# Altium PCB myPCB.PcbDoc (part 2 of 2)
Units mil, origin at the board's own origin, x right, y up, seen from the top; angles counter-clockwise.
Board outline 3914 x 3499.3 mil, 2 copper layers (Top Layer, Bottom Layer); 61 components, 196 nets, 504 pads, 76 vias.
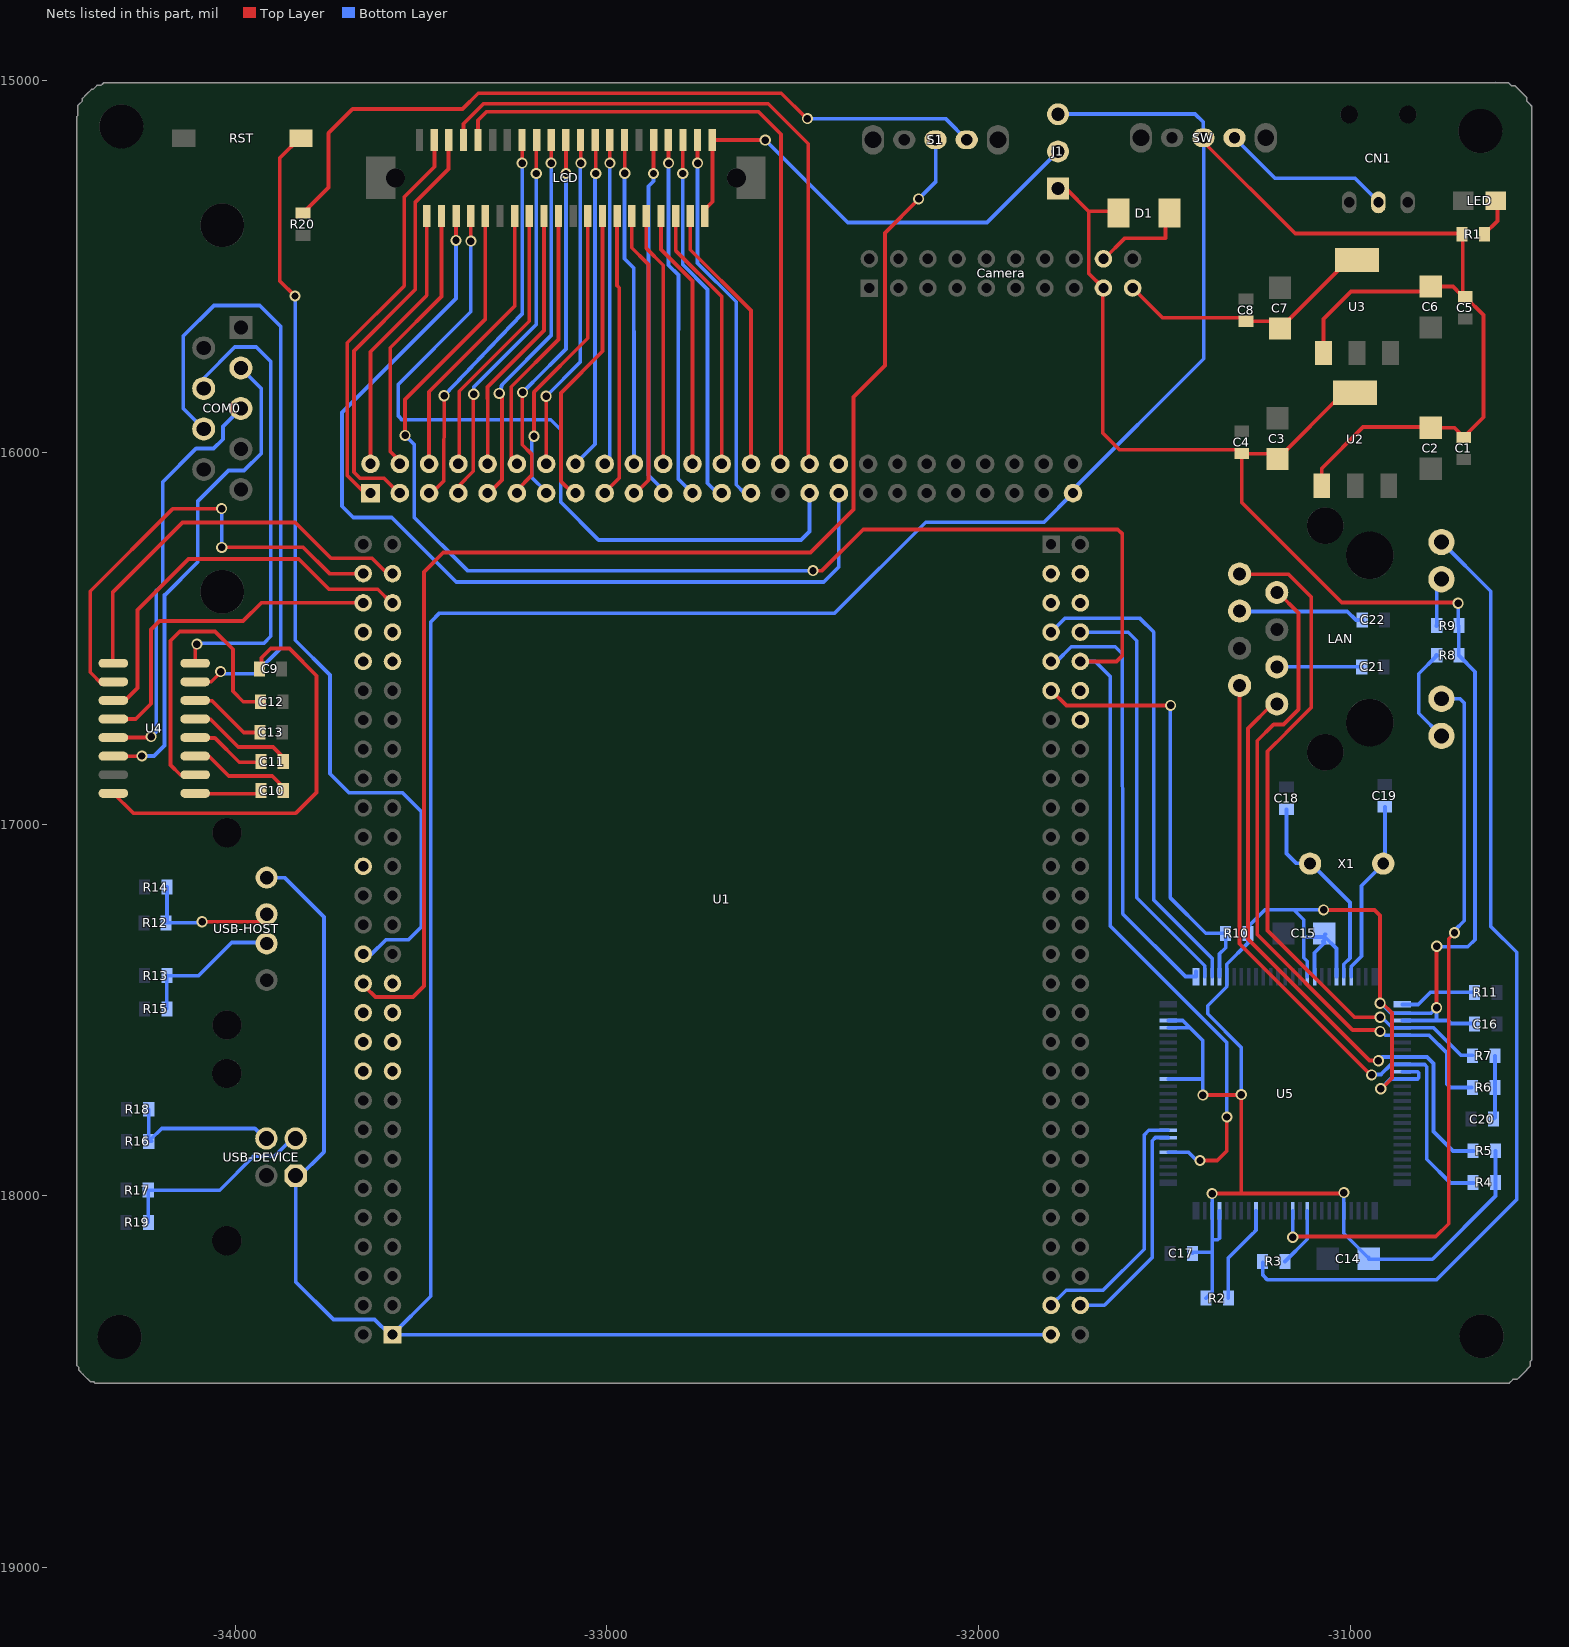
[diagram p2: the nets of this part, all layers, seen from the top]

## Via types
v1: diameter 30, hole 20, Top Layer to Bottom Layer, 75 vias
v2: diameter 30, hole 20, Top Layer to Bottom Layer, tented top, 1 vias

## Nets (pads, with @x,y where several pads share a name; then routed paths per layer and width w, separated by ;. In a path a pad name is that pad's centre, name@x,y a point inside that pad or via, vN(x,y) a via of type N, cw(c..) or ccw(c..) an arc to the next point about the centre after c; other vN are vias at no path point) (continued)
LDATA14: U1.PC53 U5.83 | length 690.5
  Bottom Layer w10: U1.PC53@-31805.13,-18294.87 -31764.51,-18254.24 -31665.07,-18254.24 -31554.69,-18143.85 -31554.69,-17836.42 -31542.12,-17823.86 U5.83@-31489.87,-17823.86
LDATA15: U1.PC54 U5.82 | length 607.4
  Bottom Layer w10: U1.PC54@-31726.39,-18294.87 -31661.68,-18294.87 -31533.08,-18166.26 -31533.08,-17852.21 -31524.41,-17843.54 U5.82@-31489.87,-17843.54
LEND: U1.PB34
LNGCS1: U1.PC3
LNGCS2: U1.PC5
LNGCS3: U1.PC4
LNGCS4: U1.PC7 U5.3 | length 1298.6
  Bottom Layer w10: U1.PC7@-31805.13,-16483.84 -31768.11,-16446.82 -31566.03,-16446.82 -31529.07,-16483.77 -31529.07,-16493.32 -31529.12,-17168.46 -31529.12,-17204.69 -31371.76,-17362.05 U5.3@-31371.76,-17410.47
LNOE: U1.PC9 U5.1 | length 1196.2
  Bottom Layer w10: U1.PC9@-31805.13,-16562.58 -31790.16,-16562.58 -31750.81,-16523.24 -31632.2,-16523.24 -31613.44,-16542 -31613.44,-16560.89 -31612.32,-17241.7 -31443.55,-17410.47 U5.1@-31415.06,-17410.47 U5.1@-31415.06,-17396.94
LNWBE1: U1.PC6
LNWE: U1.PC8 U5.2 | length 1140.9
  Bottom Layer w10: U1.PC8@-31726.39,-16483.84 -31597.49,-16483.84 -31574.45,-16506.88 -31574.45,-16509.06 -31574.38,-17182.39 -31574.38,-17198.34 -31391.44,-17381.28 U5.2@-31391.44,-17410.47
M_NRESET: RST.1 U1.PA28 | length 2589.4
  Top Layer w10: v1(-33839.13,-15579.5) -33880.4,-15538.23 -33880.4,-15208.79 -33823.2,-15151.59 RST.1@-33823.2,-15160.13
  Bottom Layer w10: v1@-33838.78,-15575.77 -33838.23,-15576.31 -33838.23,-16505.61 -33744.71,-16599.13 -33744.71,-16864.7 -33693.73,-16915.68 -33549.97,-16915.68 -33499.52,-16966.13 -33499.52,-17277 -33533.59,-17311.07 -33594.28,-17311.07 -33633.19,-17349.98 U1.PA28@-33655.53,-17349.98
NCTS0: U1.PA53 U4.9 | length 1085.4
  Top Layer w10: U4.9@-34327.69,-16567.44 -34329,-16566.13 -34329,-16376 -34141.97,-16188.97 -33838.12,-16188.97 -33741.85,-16285.24 -33632.17,-16285.24 -33591.04,-16326.36 U1.PA53@-33576.79,-16326.36 U1.PA53@-33576.79,-16319.49
NETACT: LAN.10 U5.62 | length 1991.1
  Top Layer w10: v1@-31156.35,-18109.93 -30769.96,-18109.93 -30735.34,-18075.31 -30735.34,-17308.52 v1@-30719.9,-17293.08
  Bottom Layer w10: U5.62@-31155.22,-18040.39 -31155.22,-18111.48 v1(-31155.03,-18111.67) ; LAN.10@-30754.84,-16663.02 -30704.77,-16663.02 -30693.48,-16674.31 -30693.48,-17260.36 -30718.16,-17285.04 v1@-30718.16,-17293.79
  other v1: -30719.81,-17292.55
NetC10_1: C10.1 U4.3 | length 290.7
  Top Layer w10: U4.3@-34123.69,-16818.44 -34107.69,-16818.44 -34069.56,-16818.44 -34017,-16871 -33900,-16871 C10.1@-33868,-16903
NetC10_2: C10.2 U4.1 | length 193.1
  Top Layer w10: U4.1@-34123.69,-16918.44 -34107.69,-16918.44 -33935.44,-16918.44 C10.2@-33932,-16915
NetC11_1: C11.1 U4.5 | length 294.8
  Top Layer w10: U4.5@-34123.69,-16718.44 -34107.69,-16718.44 -34066.56,-16718.44 -33992,-16793 -33898,-16793 C11.1@-33871,-16820
NetC11_2: C11.2 U4.4 | length 218.8
  Top Layer w10: U4.4@-34123.69,-16768.44 -34107.69,-16768.44 -34054.56,-16768.44 -33989,-16834 C11.2@-33932,-16834
NetC12_2: C12.2 U4.2 | length 808.6
  Top Layer w10: U4.2@-34107.69,-16867.44 -34147.56,-16867.44 -34174,-16841 -34174,-16507 -34149,-16482 -34054,-16482 -34006,-16530 -34006,-16643 -33978,-16671 ; -33978.21,-16671.21 C12.2@-33931.74,-16671.21
NetC13_2: C13.2 U4.6 | length 225.1
  Top Layer w10: U4.6@-34123.69,-16668.44 -34107.69,-16668.44 -34062.56,-16668.44 -33977,-16754 C13.2@-33934,-16754
NetC18_1: C18.1 U5.21 X1.1 | length 550.6
  Bottom Layer w10: C18.1@-31171.58,-16960.26 -31171.58,-17079.57 -31145.94,-17105.21 -31106.79,-17105.21 -31000.78,-17211.22 -31000.78,-17360.81 -31017.46,-17377.49 U5.21@-31017.46,-17410.29
NetC19_1: C19.1 U5.22 X1.2 | length 494.8
  Bottom Layer w10: U5.22@-30997.74,-17410.47 -30997.74,-17383.23 -30970.22,-17355.71 -30970.22,-17166.22 -30906.79,-17102.79 -30906.79,-16954.28 C19.1@-30907.42,-16953.65
NetC20_1: C20.1 R6.1 R7.1 | length 169.8
  Bottom Layer w10: C20.1@-30613.78,-17792.09 -30611.01,-17789.33 R6.1@-30611.01,-17708.68 R7.1@-30611.01,-17623.48
NetC21_1: C21.1 LAN.3 | length 229.9
  Bottom Layer w10: LAN.3@-31197.76,-16577.2 -30968.43,-16577.2 C21.1@-30968.03,-16577.59
NetC22_1: C22.1 LAN.6 | length 340.3
  Bottom Layer w10: LAN.6@-31298,-16428 -31008,-16428 -30984.6,-16451.4 C22.1@-30967.38,-16451.4
NetCN1_2: CN1.2 SW.2 | length 480.8
  Top Layer w10: CN1.2@-30936.09,-15343.93 -30924.48,-15332.33 CN1.2@-30924.48,-15327.53
  Bottom Layer w10: SW.2@-31311.36,-15153.89 -31202.48,-15262.76 -30987.44,-15262.76 CN1.2@-30923.37,-15326.83
NetLAN_9: LAN.9 R8.1 | length 262
  Bottom Layer w10: R8.1@-30769.24,-16546.76 R8.1@-30768,-16545.53 ; R8.1@-30768,-16548 -30816,-16596 -30816,-16701.87 LAN.9@-30754.84,-16763.02
NetLAN_11: LAN.11 R9.1 | length 132.9
  Bottom Layer w10: R9.1@-30768,-16468 -30766.74,-16466.74 -30767.67,-16465.8 -30767.67,-16354.2 LAN.11@-30754.84,-16341.37
NetLED_1: LED.1 R1.1 | length 96.1
  Top Layer w10: R1.1@-30639.47,-15413.42 -30604,-15377.95 LED.1@-30604,-15332
NETLINK: LAN.12 R3.1 | length 2670
  Bottom Layer w10: R3.1@-31235.61,-18179.73 -31235.92,-18180.05 -31235.92,-18212.18 -31235.22,-18212.89 ; -31234.93,-18213.95 -31222.52,-18226.36 -30768.79,-18226.36 -30588.89,-18046.46 ; LAN.12@-30756,-16242 LAN.12@-30755.74,-16242.26 ; LAN.12@-30756,-16240 -30621.96,-16374.04 -30621.96,-17275.58 -30552.46,-17345.08 -30552.46,-17365.13 ; -30589.49,-18047 -30552.36,-18009.88 -30552.36,-17361.5
NetR2_1: R2.1 U5.67 | length 266.5
  Bottom Layer w10: R2.1@-31328.1,-18275.59 -31328.1,-18166.74 -31263.46,-18102.1 -31262.73,-18102.1 -31253.65,-18093.01 U5.67@-31253.65,-18040.39
NetR3_2: R3.2 U5.60 | length 168.1
  Bottom Layer w10: R3.2@-31175.92,-18176.81 -31115.89,-18116.77 -31115.89,-18094.17 ; -31115.86,-18101.46 U5.60@-31115.86,-18040.9
NetR11_2: R11.2 U5.26 | length 210.7
  Bottom Layer w10: U5.26@-30859.94,-17485.28 -30817.04,-17485.28 -30784.62,-17452.85 R11.2@-30662.67,-17452.85
NetR12_1: R12.1 R14.1 USB-HOST.2 | length 374.4
  Top Layer w10: v1(-34088.87,-17262.79) -33936.07,-17262.79 USB-HOST.2@-33917.08,-17243.79
  Bottom Layer w10: R12.1@-34185.63,-17265.97 -34093.5,-17265.97 v1@-34088.88,-17261.34 ; R14.1@-34183.47,-17169.58 -34183.47,-17263.53 R12.1@-34182,-17265
NetR13_1: R13.1 R15.1 USB-HOST.3 | length 398.9
  Bottom Layer w10: R15.1@-34183.69,-17497.31 -34183.69,-17411.83 -34185.55,-17409.97 R13.1@-34183.52,-17407.94 ; R13.1@-34183.69,-17407.94 R13.1@-34183.52,-17407.94 ; R13.1@-34182.63,-17407.05 R13.1@-34183.52,-17407.94 ; USB-HOST.3@-33914.07,-17318.51 -34009.43,-17318.51 -34098.87,-17407.94 R13.1@-34183.52,-17407.94
NetR16_2: R16.2 R18.2 USB-DEVICE.3 | length 450.1
  Bottom Layer w10: R18.2@-34232.54,-17767.36 -34232.54,-17845.46 R16.2@-34228.39,-17849.61 ; USB-DEVICE.3@-33924.76,-17853.76 -33916.55,-17845.55 USB-DEVICE.3@-33916,-17845 ; USB-DEVICE.3@-33919,-17847 -33947,-17819 -34197.78,-17819 R16.2@-34228.39,-17849.61 ; R16.2@-34228.39,-17849.61 R16.2@-34232.54,-17853.76 -34224.24,-17853.76 R16.2@-34228.39,-17849.61
NetR17_2: R17.2 R19.1 USB-DEVICE.2 | length 533.2
  Bottom Layer w10: R19.1@-34233.95,-18070.42 -34233.63,-18070.1 R17.2@-34233.63,-17985.03 -34041.53,-17985.03 -33950.5,-17894 -33894,-17894 -33845,-17845 USB-DEVICE.2@-33844,-17845
NetR20_1: R20.1 S1.4 | length 2055.5
  Top Layer w10: R20.1@-33817.71,-15356.6 -33748.91,-15287.8 -33748.91,-15141.34 -33684.03,-15076.46 -33388.48,-15076.46 -33345.83,-15033.81 -32530.76,-15033.81 v1@-32464.46,-15100.12
  Bottom Layer w10: v1(-32460.54,-15102.37) -32089.07,-15102.37 S1.4@-32029.82,-15161.61
NRESET: LCD.10 U1.PC10 U5.80 | length 5061.1
  Top Layer w10: v1(-33542.84,-15954.71) -33543.31,-15857.81 -33326.87,-15641.37 LCD.10@-33326.87,-15364.16 ; v1(-32445.51,-16318.33) -32421.42,-16318.33 -32310.52,-16207.42 -31625.47,-16207.42 -31613.26,-16219.62 -31613.26,-16546.57 -31629.27,-16562.58 U1.PC10@-31726.39,-16562.58 U1.PC10@-31726.39,-16569.6 ; v2(-31404.42,-17905.16) -31357.96,-17905.16 -31332.24,-17879.44 v1(-31332.24,-17788.1)
  Bottom Layer w10: v1(-33542.84,-15954.71) -33518.28,-15979.26 -33518.28,-16175.26 -33375.22,-16318.33 v1(-32445.51,-16318.33) ; U1.PC10@-31726.39,-16562.58 -31686.15,-16562.58 -31646.21,-16602.52 -31646.21,-17273.63 -31332.24,-17587.6 v1(-31332.24,-17788.1) ; U5.80@-31489.87,-17882.91 -31435.12,-17882.91 -31412.88,-17905.16 v2(-31404.42,-17905.16)
NRTS0: U1.PA54 U4.10 | length 1226.9
  Top Layer w10: U4.10@-34358,-16624 -34390,-16592 -34390,-16374 -34168.23,-16152.23 v1@-34037.23,-16152.23 ; v1(-34036.21,-16255.78) -33817.15,-16255.78 -33746.56,-16326.36 U1.PA54@-33655.53,-16326.36
  Bottom Layer w10: v1(-34036.21,-16255.78) v1@-34036.21,-16151.65 ; U1.PA54@-33655.53,-16326.36 U1.PA54@-33650.52,-16326.36
  other v1: -34036.43,-16151.43
NWAIT: R10.2 U1.PC11 U5.4 | length 1167.5
  Top Layer w10: U1.PC11@-31805.13,-16641.32 -31803.66,-16641.32 -31763.92,-16681.06 v1(-31483.46,-16681.06)
  Bottom Layer w10: v1(-31483.46,-16681.06) -31484.13,-16681.73 -31484.13,-17198.71 -31388.76,-17294.08 R10.2@-31335.37,-17294.08 -31335.37,-17332.56 -31351.71,-17348.91 -31351.71,-17373.43 ; U5.4@-31352.07,-17410.47 U5.4@-31352.07,-17410 ; U5.4@-31352,-17410 -31352,-17373.43
NXDACK0: U1.PC12
NXDREQ0: U1.PC14
OM0: S1.3 U1.PA26 | length 3631.4
  Top Layer w10: U1.PA26@-33649.86,-17428.72 -33649.86,-17438.42 -33622.84,-17465.44 -33521.57,-17465.44 -33492.11,-17435.98 -33492.11,-16321.8 -33440.13,-16269.82 -32452.44,-16269.82 -32336.76,-16154.14 -32336.76,-15851.12 -32252,-15766.36 -32252,-15664.07 ; -32251.95,-15664.02 -32251.95,-15409.98 v1@-32160.9,-15318.92
  Bottom Layer w10: U1.PA26@-33655.53,-17428.72 U1.PA26@-33640.24,-17428.72 ; v1(-32161.49,-15318.32) -32114.98,-15271.81 S1.3@-32114.98,-15159.29
RSCTS0: COM0.7 U4.8 | length 1246
  Top Layer w10: U4.8@-34107.69,-16567.44 -34107.69,-16529.69 v1@-34106,-16528
  Bottom Layer w10: v1@-34104,-16514 -33922.87,-16514 -33904,-16495.13 -33904,-15756 -33943,-15717 -34001,-15717 -34084.63,-15800.63 COM0.7@-34084.63,-15828.16
  other v1: -34103,-16516
RSRTS0: COM0.8 U4.7 | length 1769.6
  Top Layer w10: U4.7@-34123.69,-16618.44 U4.7@-34082.44,-16618.44 ; U4.7@-34107.69,-16617.44 -34064.44,-16617.44 v1@-34039,-16592
  Bottom Layer w10: COM0.8@-34084.63,-15937.16 -34140,-15881.79 -34140,-15688 -34057,-15605 -33934,-15605 -33877,-15662 -33877,-16526.11 -33946.89,-16596 v1@-34040,-16596
  other v1: -34039,-16590
RSRXD0: COM0.3 U4.13 | length 1108.4
  Top Layer w10: U4.13@-34327.69,-16767.44 -34229.44,-16767.44 v1@-34229,-16767
  Bottom Layer w10: v1(-34226,-16765) -34212,-16751 -34212,-16371 ; -34210,-16371 -34195,-16356 -34195,-16080 -34105,-15990 -34058,-15990 -34033,-15965 -34033,-15930.53 COM0.3@-33984.63,-15882.16
RSTXD0: COM0.2 U4.14 | length 1306.4
  Top Layer w10: U4.14@-34327.69,-16817.44 -34266.56,-16817.44 -34266,-16818
  Bottom Layer w10: v1(-34251,-16817) -34218,-16817 -34190,-16789 -34190,-16388 ; -34190,-16384 -34189,-16384 -34101,-16296 -34101,-16132 -34018,-16049 -33976,-16049 -33930,-16003 -33930,-15828 -33984.73,-15773.27 COM0.2@-33988,-15770
RX+: LAN.8 R7.2 U5.29 | length 1854.3
  Top Layer w10: LAN.8@-31298,-16328 -31166,-16328 -31105.01,-16388.99 -31105.01,-16686.46 -31172.47,-16753.92 ; -31172.67,-16754.29 -31222.56,-16804.19 -31222.56,-17286.46 -30989.03,-17520 v1(-30920,-17520)
  Bottom Layer w10: v1(-30920,-17520) -30915.45,-17520 -30887.19,-17548.27 U5.29@-30859.94,-17548.27 ; U5.29@-30859.94,-17548 -30775.94,-17548 -30701.53,-17622.41 R7.2@-30671.47,-17622.41
RX-: LAN.7 R6.2 U5.30 | length 1802
  Top Layer w10: LAN.7@-31194,-16378 -31139.62,-16432.38 -31139.62,-16691.62 -31180,-16732 -31206.36,-16732 -31250.36,-16776 -31250.36,-17297.44 -30993.8,-17554 v1@-30920,-17554
  Bottom Layer w10: v1@-30922,-17554 -30920,-17554 -30906,-17568 -30788,-17568 -30740.15,-17615.85 -30740.15,-17699.85 -30731.05,-17708.95 R6.2@-30673.25,-17708.95
  other v1: -30920,-17558
RXD0: U1.PA52 U4.12 | length 918.8
  Top Layer w10: U4.12@-34327.69,-16717.44 -34267.3,-16717.44 -34226.57,-16676.71 -34226.57,-16476.61 -34203.83,-16453.87 -33978.71,-16453.87 -33929.94,-16405.1 U1.PA52@-33655.53,-16405.1
RXD1: U1.PA50
RXD2: U1.PA48 | length 19
  Bottom Layer w10: U1.PA48@-33674.55,-16562.58 U1.PA48@-33655.53,-16562.58
SDCLK: U1.PA20
SDCMD: U1.PA21
SDDATA0: U1.PA24
SDDATA1: U1.PA25
SDDATA2: U1.PA22
SDDATA3: U1.PA23
TSXM: LCD.5 U1.PB3 | length 1145.9
  Top Layer w10: U1.PB3@-33557.1,-16109.83 -33557.1,-16109.1 -33560.33,-16109.1 -33599.67,-16069.76 -33664.23,-16069.76 -33680.31,-16053.69 -33680.31,-15727.43 -33515.86,-15562.97 -33515.86,-15327.86 -33426,-15238 LCD.5@-33426,-15160
TSXP: LCD.4 U1.PB4 | length 734.4
  Top Layer w10: U1.PB4@-33557.1,-16031.09 -33557.1,-16023.32 -33582.53,-15997.89 -33582.53,-15718.77 -33444.98,-15581.23 LCD.4@-33444.98,-15364.16
TSYM: LCD.3 U1.PB1 | length 1081.7
  Top Layer w10: U1.PB1@-33635.84,-16109.83 -33651.11,-16109.83 -33698.31,-16062.62 -33698.31,-15705.19 -33545.4,-15552.28 -33545.4,-15313.29 -33464,-15231.9 LCD.3@-33464,-15160
TSYP: LCD.2 U1.PB2 | length 729.7
  Top Layer w10: U1.PB2@-33635.84,-16031.09 -33635.84,-15729.31 -33484.35,-15577.82 LCD.2@-33484.35,-15364.16
TX+: LAN.1 R5.1 U5.33 | length 1632.7
  Top Layer w10: LAN.1@-31198,-16678 -31210,-16678 -31275.24,-16743.24 -31275.24,-17309.31 -30948.54,-17636 v1@-30920,-17636
  Bottom Layer w10: v1(-30924.31,-17636.88) -30914.44,-17627.01 U5.33@-30859.94,-17627.01 -30793.39,-17627.01 -30776.15,-17644.25 -30776.15,-17827.28 -30723.76,-17879.67 R5.1@-30668.51,-17879.67
TX-: LAN.2 R4.1 U5.34 | length 1763.8
  Top Layer w10: LAN.2@-31298,-16630 -31298,-17322.23 -30949.1,-17671.13 -30938.87,-17671.13 v1@-30936,-17674
  Bottom Layer w10: v1@-30942.55,-17673.93 -30917.93,-17673.93 ; -30918,-17674 -30917.93,-17673.93 ; -30917.41,-17673.93 -30917.93,-17673.93 ; R4.1@-30668.57,-17965.88 -30730.16,-17965.88 -30794.17,-17901.87 -30794.17,-17653.07 -30800.55,-17646.69 U5.34@-30859.94,-17646.69 -30890.69,-17646.69 -30917.93,-17673.93
  other v1: -30942.77,-17675.03
TXD0: U1.PA51 U4.11 | length 1070.5
  Top Layer w10: U4.11@-34317,-16669 -34298,-16669 -34263,-16634 -34263,-16424 -34125.85,-16286.85 -33828.97,-16286.85 -33747.6,-16368.22 -33616.42,-16368.22 -33579.54,-16405.1 U1.PA51@-33576.79,-16405.1
TXD1: U1.PA49
TXD2: U1.PA47
VCC: C9.1 U4.16 | length 1114.5
  Top Layer w10: U4.16@-34327.69,-16917.44 -34274.45,-16970.68 -33836.68,-16970.68 -33781,-16915 -33781,-16600.92 -33853.92,-16528 -33904,-16528 -33929,-16553 C9.1@-33929,-16573
VCLK: LCD.6 U1.PB33 | length 2544.8
  Top Layer w10: v1(-33406,-15430) LCD.6@-33406,-15364
  Bottom Layer w10: v1(-33406,-15430) -33406,-15586 -33712.81,-15892.81 -33712.81,-16145.3 -33682.63,-16175.47 -33578.84,-16175.47 -33405.49,-16348.83 -32416.45,-16348.83 -32376,-16308.37 U1.PB33@-32376,-16109.83
VD0: LCD.39 U1.PB27 | length 1038
  Top Layer w10: v1(-32756,-15222) LCD.39@-32756.01,-15159.43 ; U1.PB27@-32630.1,-16109.83 U1.PB27@-32612.22,-16109.83
  Bottom Layer w10: v1(-32756,-15222) -32756,-15491.17 -32652.17,-15595 -32652.26,-15837.1 -32652.26,-16087.04 -32629.47,-16109.83 U1.PB27@-32612.22,-16109.83
VD1: LCD.38 U1.PB28 | length 734.6
  Top Layer w10: LCD.38@-32775.69,-15364.16 -32775.69,-15455.05 -32612.22,-15618.52 U1.PB28@-32612.22,-16031.09
VD2: LCD.37 U1.PB25 | length 1017
  Top Layer w10: v1(-32796,-15250) LCD.37@-32796,-15160 ; U1.PB25@-32708.05,-16109.83 U1.PB25@-32690.96,-16109.83
  Bottom Layer w10: v1(-32796,-15250) -32796,-15494.86 -32729.01,-15561.84 ; -32729.35,-15562.18 -32729.35,-16083.08 -32702.6,-16109.83 U1.PB25@-32690.96,-16109.83
VD3: LCD.36 U1.PB26 | length 717.1
  Top Layer w10: LCD.36@-32815.06,-15364.16 -32815.06,-15456.76 -32691.82,-15580 ; U1.PB26@-32690.96,-16031.09 -32690.96,-15580.86
VD4: LCD.35 U1.PB23 | length 999.7
  Top Layer w10: v1(-32834,-15222) LCD.35@-32834,-15158 ; U1.PB23@-32775.4,-16109.83 U1.PB23@-32769.7,-16109.83
  Bottom Layer w10: v1(-32834,-15222) -32834,-15496.63 -32807.53,-15523.1 -32807.83,-15820.54 ; -32807.84,-15835.96 -32807.83,-15820.57 ; U1.PB23@-32769.7,-16109.83 -32807.83,-16071.7 -32807.83,-15820.54
VD5: LCD.34 U1.PB24 | length 701.9
  Top Layer w10: LCD.34@-32854.43,-15364.16 -32854.43,-15454.2 -32769.57,-15539.07 ; U1.PB24@-32769.7,-16031.09 -32769.7,-15539.19
VD6: LCD.33 U1.PB21 | length 976.3
  Top Layer w10: v1(-32874.53,-15250) LCD.33@-32874.53,-15158
  Bottom Layer w10: v1(-32874.53,-15250) -32874.53,-15270.53 -32888.05,-15284.05 -32888.05,-16061.51 -32848.44,-16101.11 U1.PB21@-32848.44,-16109.83 U1.PB21@-32850.93,-16109.83
VD7: LCD.32 U1.PB22 | length 685.9
  Top Layer w10: LCD.32@-32893.8,-15364.16 -32893.8,-15451.41 -32848.27,-15496.94 -32848.44,-15497.11 U1.PB22@-32848.44,-16031.09
VD8: LCD.30 U1.PB19 | length 783.5
  Top Layer w10: LCD.30@-32933.17,-15364.16 -32933.17,-15449.47 -32893.35,-15489.29 -32887.94,-15494.7 -32887.94,-16075.38 -32922.39,-16109.83 U1.PB19@-32927.18,-16109.83
VD9: LCD.29 U1.PB20 | length 878.7
  Top Layer w10: v1(-32951.75,-15249.15) LCD.29@-32951.75,-15163.15
  Bottom Layer w10: v1(-32951.75,-15249.15) -32952.89,-15253.11 -32952.89,-15479.08 -32927.37,-15504.6 -32927.18,-15838.7 U1.PB20@-32927.18,-16031.09
VD10: LCD.28 U1.PB17 | length 764.5
  Top Layer w10: U1.PB17@-33005.92,-16109.83 -33005.92,-16108.38 -32966.55,-16069.01 -32966.55,-15557.62 -32972.54,-15551.63 LCD.28@-32972.54,-15364.16
VD11: LCD.27 U1.PB18 | length 878.9
  Top Layer w10: v1(-32992,-15222) LCD.27@-32992,-15158
  Bottom Layer w10: U1.PB18@-33005.92,-16031.09 -32992,-16017.17 v1(-32992,-15222)
VD12: LCD.26 U1.PB15 | length 810.6
  Top Layer w10: -33123.42,-15839.94 -33123.42,-16078.25 -33091.84,-16109.83 U1.PB15@-33084.66,-16109.83 ; -33122.34,-15838.86 -33011.91,-15728.44 LCD.26@-33011.91,-15364.16
VD13: LCD.25 U1.PB16 | length 876.9
  Top Layer w10: v1(-33030,-15250) LCD.25@-33030,-15162
  Bottom Layer w10: U1.PB16@-33084.66,-16031.09 -33032,-15978.42 v1@-33032,-15264
VD14: LCD.24 U1.PB13 | length 824.5
  Top Layer w10: v1(-33196.09,-15957) -33196.09,-15838.11 -33051.28,-15693.3 LCD.24@-33051.28,-15364.16
  Bottom Layer w10: v1(-33196.09,-15957) -33202.48,-15963.39 -33202.48,-16067.26 -33163.4,-16106.33 U1.PB13@-33163.4,-16109.83
VD15: LCD.23 U1.PB14 | length 904.9
  Top Layer w10: U1.PB14@-33163.4,-16031.09 v1(-33163.4,-15849.4) ; v1(-33070,-15222) LCD.23@-33070,-15162
  Bottom Layer w10: v1(-33163.4,-15849.4) -33072,-15758 v1@-33072,-15224
VD16: LCD.21 U1.PB11 | length 1022.6
  Top Layer w10: U1.PB11@-33242.14,-16109.83 -33242.14,-16101.81 -33202.48,-16062.15 -33202.48,-16004.62 -33227.62,-15979.49 v1@-33227.62,-15842.08 ; v1(-33110,-15250) LCD.21@-33110,-15160
  Bottom Layer w10: v1(-33226.83,-15838.83) -33200.29,-15812.28 -33200.07,-15812.16 ; -33200.61,-15812.71 -33110,-15722.09 v1(-33110,-15250)
VD17: LCD.20 U1.PB12 | length 725.8
  Top Layer w10: U1.PB12@-33242.14,-16031.09 -33257.19,-16016.03 -33257.19,-15823.69 -33130.02,-15696.52 LCD.20@-33130.02,-15364.16
VD18: LCD.19 U1.PB9 | length 1033.2
  Top Layer w10: U1.PB9@-33320.88,-16103.53 U1.PB9@-33320.88,-16109.83 -33317.29,-16109.83 -33282.01,-16074.55 -33282.01,-15849.04 v1(-33289.41,-15841.65) ; v1(-33150,-15222) LCD.19@-33150,-15160
  Bottom Layer w10: v1(-33289.41,-15841.65) -33282.12,-15818.12 -33150,-15686 v1(-33150,-15222)
VD19: LCD.18 U1.PB10 | length 729.8
  Top Layer w10: U1.PB10@-33320.88,-16031.09 -33320.88,-15855.12 -33321,-15855 -33321,-15824.23 -33169.39,-15672.62 LCD.18@-33169.39,-15364.16
VD20: LCD.17 U1.PB7 | length 1036.1
  Top Layer w10: U1.PB7@-33399.62,-16109.83 -33399.62,-16091.64 -33359.23,-16051.25 v1@-33359.23,-15843.88 ; v1(-33190,-15250) LCD.17@-33190,-15160
  Bottom Layer w10: v1(-33358.11,-15843.88) -33358,-15824 -33190,-15656 v1(-33190,-15250)
VD21: LCD.16 U1.PB8 | length 746
  Top Layer w10: U1.PB8@-33399.62,-16031.09 -33396.9,-16028.37 -33396.9,-15835.49 -33208.76,-15647.35 LCD.16@-33208.76,-15364.16
VD22: LCD.15 U1.PB5 | length 1065.1
  Top Layer w10: U1.PB5@-33478.36,-16109.83 -33471.62,-16109.83 -33438.97,-16077.18 v1(-33437.86,-15848.04) ; v1(-33228,-15222) LCD.15@-33228,-15160
  Bottom Layer w10: U1.PB5@-33478.36,-16109.83 U1.PB5@-33478.36,-16108.02 ; v1@-33438.97,-15838.97 v1(-33437.86,-15848.04) -33228,-15628 v1(-33228,-15222)
VD23: LCD.14 U1.PB6 | length 762.5
  Top Layer w10: U1.PB6@-33478.36,-16031.09 -33478.36,-15836.99 -33248,-15606.63 LCD.14@-33248,-15364
VDD5V: C1.1 C2.1 C5.1 C6.1 J1.3 R1.2 SW.3 U1.PA1 U1.PB49 U1.PC55 U2.3 U3.3 USB-DEVICE.1 USB-HOST.1 | length 11109.3
  Top Layer w10: SW.3@-31395.38,-15151.94 -31395.38,-15164.37 -31148.39,-15411.36 -30702.64,-15411.36 R1.2@-30700,-15414 ; U2.3@-31077,-16099 -31077,-16043.37 -30965.63,-15932 C2.1@-30784,-15932 ; U3.3@-31072,-15733 -31072,-15641.41 -30998.25,-15567.66 -30795.66,-15567.66 C6.1@-30784,-15556 ; C2.1@-30784,-15934 -30720,-15934 C1.1@-30694,-15960 ; C6.1@-30784,-15554 -30724,-15554 C5.1@-30702,-15576 ; C5.1@-30699.47,-15574.53 C5.1@-30692,-15582 ; R1.2@-30699.47,-15413.42 -30697.73,-15415.16 -30697.73,-15577.49 -30697.22,-15578 C5.1@-30682,-15578 ; C1.1@-30696,-15960 -30642,-15906 -30642,-15630.53 C5.1@-30690.79,-15581.74
  Bottom Layer w10: USB-HOST.1@-33915.38,-17144.22 -33866.78,-17144.22 -33861.6,-17149.4 ; -33864.47,-17146.35 -33761,-17249.82 -33761,-17882 USB-DEVICE.1@-33832,-17953 ; USB-DEVICE.1@-33837.35,-17946.02 -33837.35,-18231.28 -33735.8,-18332.83 -33625.01,-18332.83 -33584.23,-18373.61 U1.PC55@-31805.13,-18373.61 ; U1.PA1@-33576.79,-18373.61 -33473.81,-18270.62 -33473.81,-16456.34 -33450.14,-16432.68 -32387.14,-16432.68 -32142.34,-16187.89 -31824.14,-16187.89 U1.PB49@-31746.08,-16109.83 -31746.08,-16100.08 -31394.28,-15748.27 -31394.28,-15710.77 -31394.39,-15710.66 -31394.39,-15638.45 -31394.28,-15638.34 -31394.28,-15598.27 -31394.21,-15598.21 -31394.21,-15156.25 -31394.47,-15155.98 SW.3@-31394.47,-15154.43 ; J1.3@-31784.85,-15089.77 -31417.76,-15089.77 -31395.36,-15112.18 SW.3@-31395.36,-15153.89
VDD18V: C7.1 C8.1 Camera.19 U3.4 | length 678.1
  Top Layer w10: Camera.19@-31585.41,-15558.1 -31505.51,-15638 -31280.21,-15638 C8.1@-31280,-15638 ; C8.1@-31280.21,-15647.26 C7.1@-31193.74,-15647.26 ; C7.1@-31189,-15667 U3.4@-31010,-15488
VDD33V: C3.1 C4.1 C14.1 C15.1 C16.1 C17.1 Camera.17 D1.1 J1.1 R2.2 R4.2 R5.2 R8.2 R9.2 R10.1 U2.4 U5.5 U5.16 U5.17 U5.20 U5.27 U5.28 U5.35 U5.36 U5.55 U5.72 U5.73 U5.90 U5.97 U5.98 | length 8393.9
  Top Layer w10: J1.1@-31786.23,-15293.11 -31762.2,-15293.11 -31704,-15351.32 -31704,-15518.25 Camera.17@-31664.15,-15558.1 ; -31701.22,-15351.32 -31630.33,-15351.32 D1.1@-31629.74,-15350.72 ; Camera.17@-31666,-15558 -31666,-15948 -31620.74,-15993.26 -31292.21,-15993.26 -31292.21,-16135.15 -31023.36,-16404 v1@-30710,-16404 ; v1@-31396.22,-17729.24 v1@-31294.73,-17729.24 ; v1(-31371.76,-17994.24) -31021.89,-17994.24 v1@-31018.25,-17990.6 ; v1(-31293.32,-17727.84) -31293.32,-17993.68 -31292.76,-17994.24 ; C4.1@-31292,-16004 C3.1@-31212,-16004 ; C3.1@-31196,-16018 -31018,-15840 U2.4@-30987,-15840 ; v1(-31071.71,-17231.15) -30935.23,-17231.15 -30920,-17246.38 v1(-30920,-17482) -30914,-17482 -30888,-17508 -30888,-17684 v1@-30917,-17713 ; U2.4@-31020,-15842 U2.4@-30988,-15842 ; v1(-30768.04,-17494.07) v1@-30768.04,-17329.68
  Bottom Layer w10: U5.90@-31489.87,-17686.06 -31396.76,-17686.06 -31396.66,-17685.96 ; U5.97@-31489.87,-17548 -31432.87,-17548 ; U5.98@-31489.87,-17528.58 -31450.87,-17528.58 -31396.66,-17582.8 -31396.66,-17685.96 ; C17.1@-31425.04,-18155.07 -31421.66,-18151.68 -31371.76,-18151.68 ; v1(-31396.66,-17729.24) -31396.66,-17685.96 ; R2.2@-31388.1,-18275.59 -31371.76,-18259.24 v1(-31371.76,-17994.24) ; -31371.76,-18118.68 -31356.88,-18118.68 -31352.07,-18113.87 U5.72@-31352.07,-18040.39 ; v1(-31293.32,-17727.84) -31293.32,-17601.06 -31383.79,-17510.6 -31383.79,-17489.12 -31332.39,-17437.72 -31332.39,-17377.26 -31275.37,-17320.24 R10.1@-31275.37,-17294.08 ; R10.1@-31274.39,-17275.58 -31229.39,-17230.57 v1@-31072.28,-17230.57 ; -31152.47,-17230.57 -31125.32,-17257.72 -31125.32,-17359.66 -31115.85,-17369.13 U5.16@-31115.85,-17410.47 ; -31125.32,-17303.95 -31072.15,-17303.95 C15.1@-31070,-17301.8 ; U5.17@-31096.17,-17410.47 -31096.17,-17346.17 -31070,-17320 C15.1@-31070,-17301.8 ; C15.1@-31074,-17316 C15.1@-31069,-17321 ; C15.1@-31067.88,-17296.57 C15.1@-31066.53,-17296.57 ; U5.20@-31037.11,-17410.47 -31037.11,-17334.69 C15.1@-31070,-17301.8 ; v1(-31017.43,-17991.43) -31017.43,-18100.97 -30953.14,-18165.26 C14.1@-30950.9,-18165.26 ; C14.1@-30950.3,-18170.81 -30779.3,-18170.81 -30609.54,-18001.05 R5.2@-30609.54,-17879.12 ; v1@-30918,-17482 -30891.1,-17508.9 -30782.87,-17508.9 v1(-30768.04,-17494.07) -30768.04,-17526.47 -30769.33,-17527.77 ; v1@-30917.88,-17712 -30891.94,-17686.06 -30819.01,-17686.06 -30815.72,-17682.77 -30815.72,-17669.45 -30818.79,-17666.38 U5.35@-30859.94,-17666.38 ; U5.28@-30859.94,-17528.58 -30737.11,-17528.58 -30729,-17536.69 C16.1@-30665.67,-17536.69 ; v1@-30767.68,-17330.34 -30683.82,-17330.34 -30664.65,-17311.17 -30664.65,-16590.35 -30708,-16547 -30708,-16468 -30710,-16466 v1(-30710,-16406) ; v1@-30710,-16404 v1@-30707.53,-16406.47 ; C16.1@-30667.03,-17536.69 C16.1@-30665.67,-17538.04 ; R4.2@-30610.35,-17965.12 R4.2@-30609.54,-17964.31 ; R4.2@-30609.54,-17965.33 R4.2@-30608.98,-17965.9
  other v1: -30918,-17712 -30767.68,-17328.87
VDD_CAM: Camera.18 D1.2 | length 255.9
  Top Layer w10: Camera.18@-31664.15,-15479.36 -31661.89,-15479.36 -31606.33,-15423.81 -31497.03,-15423.81 D1.2@-31497.03,-15358.05
VDDLCD: J1.2 LCD.40 LCD.41 | length 1299.2
  Top Layer w10: LCD.40@-32736.32,-15346.32 -32716,-15326 -32716,-15160 v1(-32574,-15160)
  Bottom Layer w10: v1(-32574,-15160) -32352.17,-15381.83 -31977.45,-15381.83 J1.2@-31786.17,-15190.55 ; J1.2@-31787.41,-15193.52 J1.2@-31784.89,-15191
VDDRTC: U1.PA34
VFRAME: LCD.8 U1.PB31 | length 2091.1
  Top Layer w10: v1(-33366,-15432) LCD.8@-33366,-15364
  Bottom Layer w10: v1(-33366,-15432) -33366,-15622 -33560.92,-15816.92 -33560.92,-15902.57 -33552.57,-15910.92 -33552.57,-15912.2 -33151.18,-15912.2 -33124.17,-15939.21 -33124.17,-16134.02 -33022.22,-16235.96 -32477.76,-16235.96 -32454.74,-16212.94 U1.PB31@-32454.74,-16109.83
VLINE: LCD.7 U1.PB32 | length 1900.8
  Top Layer w10: LCD.7@-33385.93,-15159.43 -33385.93,-15115.93 -33332.19,-15062.19 -32565.81,-15062.19 -32458.15,-15169.84 -32458.15,-16027.67 U1.PB32@-32454.74,-16031.09
VM: LCD.9 U1.PB30 | length 1789.6
  Top Layer w10: LCD.9@-33346.56,-15159.43 -33346.56,-15106.56 -33324,-15084.01 -32591.99,-15084.01 -32531.69,-15144.31 -32531.69,-16029.29 U1.PB30@-32533.48,-16031.09
WP_SD: U1.PA19
pads on no net: CN1.A CN1.B COM0. COM0.1 COM0.4 COM0.6 COM0.9 LAN.C LAN.D LCD.1 LCD.A LCD.B LCD.C LCD.D S1.1 S1.2 S1.5 SW.1 SW.4 SW.5 U2.2 U3.2 U5.24 U5.37 U5.38 U5.39 U5.40 U5.41 U5.43 U5.44 U5.45 U5.46 U5.47 U5.49 U5.50 U5.51 U5.52 U5.53 U5.54 U5.56 U5.57 U5.59 U5.61 U5.64 U5.65 U5.66 U5.68 U5.69 U5.70 U5.71 U5.74 U5.75 U5.77 U5.78 U5.79 U5.91 USB-DEVICE.5 USB-DEVICE.6 USB-HOST.5 USB-HOST.6
copper on no net: | length 14.5
  Top Layer w10: -30561.86,-19070 -30552.2,-19070 ; -30542.54,-19070 -30537.71,-19070

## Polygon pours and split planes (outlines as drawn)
GND on Top Layer "Bottom Layer-No Net" (solid, pour order 14): -34324,-15005 -30576,-15005 -30574.47,-15006.53 -30566.96,-15006.53 -30557.57,-15015.92 -30547.96,-15015.92 -30540.93,-15022.95 -30521.92,-15041.96 -30521.92,-15045.48 -30514.65,-15052.75 -30514.65,-15071.74 -30514.65,-15084.88 -30511.83,-15087.69 -30513.01,-15088.87 -30513.01,-18441.62 -30513.01,-18447.72 -30520.05,-18454.76 -30520.05,-18460.86 -30529.43,-18470.24 -30555.23,-18496.04 -30560.39,-18496.04 -30568.6,-18504.25 -30589.71,-18504.25 -30638.97,-18504.25 -30639.44,-18504.72 -30639.66,-18504.94 -30726.68,-18504.94 -30727.11,-18505.37 -34366.02,-18505.37 -34370.78,-18500.62 -34384.17,-18500.62 -34390.15,-18500.62 -34404.78,-18485.98 -34418.36,-18472.4 -34418.36,-18470.48 -34418.36,-18460.97 -34426.29,-18453.03 -34426.82,-18452.51 -34426.82,-18425.01 -34426.82,-15086.18 -34424.09,-15083.45 -34424.09,-15069.29 -34416.51,-15061.71 -34416.51,-15054.48 -34403.67,-15041.64 -34391.37,-15029.34 -34391.37,-15028.7 -34376.17,-15013.51 -34367.22,-15013.51 -34359.63,-15005.91 -34344.98,-15005.91 -34324.91,-15005.91 -34324,-15005
GND on Bottom Layer "Bottom Layer-No Net" (solid, pour order 16): -34312.81,-15005.55 -30573.64,-15005.55 -30570.73,-15008.46 -30561.11,-15008.46 -30555.27,-15014.29 -30549.09,-15014.29 -30532.61,-15030.78 -30517.84,-15045.55 -30517.84,-15050.35 -30517.84,-15064.09 -30513.72,-15068.21 -30509.6,-15072.33 -30509.6,-15119.38 -30509.6,-18422.62 -30513.01,-18426.03 -30515.15,-18428.17 -30515.15,-18446.94 -30515.15,-18454.19 -30525.17,-18464.21 -30539.67,-18478.7 -30539.67,-18485.31 -30546.28,-18485.31 -30559.08,-18498.11 -30561.21,-18500.24 -30575.28,-18500.24 -30584.88,-18500.24 -30590,-18505.36 -30590.21,-18505.58 -30620.28,-18505.58 -34371.67,-18505.58 -34378.07,-18499.18 -34391.5,-18499.18 -34403.02,-18487.66 -34416.03,-18474.65 -34416.03,-18468.68 -34424.98,-18459.73 -34424.98,-18450.78 -34424.98,-18424.97 -34427.32,-18422.63 -34427.32,-18352.69 -34427.32,-15097.35 -34426,-15096.02 -34426,-15073 -34418.71,-15065.72 -34418.71,-15055.65 -34402.4,-15039.34 -34400.76,-15039.34 -34388.4,-15026.97 -34375.28,-15013.85 -34371.12,-15013.85 -34363.67,-15006.4 -34344.52,-15006.4 -34325.4,-15006.4 -34324,-15005

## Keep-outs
Keep-Out Layer:
  lines w10: -34426,-15577 -34426,-18436.3 ccw(c-34357.46,-18435.77) -34356.93,-18504.3 ; -34426,-15575 -34426,-15096.02 ; -34426,-15097 cw(c-34326,-15105) -34318,-15005 ; -34357.46,-18504.31 -34300.05,-18504.31 ; -34324,-15005 -34283.25,-15005 -34217.75,-15005 -30598.58,-15005 ; -34307.66,-18504.31 -30598.21,-18504.31 ; -34183,-15005 -30602.16,-15005 ; -30600.88,-15005.02 -30590.48,-15005.3 cw(c-30592.68,-15085.96) -30512.02,-15088.16 ; -30598.23,-18504.32 ccw(c-30595.93,-18420.44) -30512.05,-18422.74 ; -30512,-18420.44 -30512,-18361 -30512,-15085.96 ; -30601,-15005 -30600.98,-15005

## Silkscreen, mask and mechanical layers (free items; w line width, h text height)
Top Overlay:
  text "Nand" at -31998.97,-15058.49 h30
  text "Nor" at -32348.39,-15061.52 h30
  text "EMBEDE_LAB" at -33483,-16181 h30
  text "ARM920T" at -32848.54,-17308.27 h60
Bottom Overlay:
  text "+" at -31000.78,-17313.23 h30
  text "+" at -30870.88,-18161.3 h30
